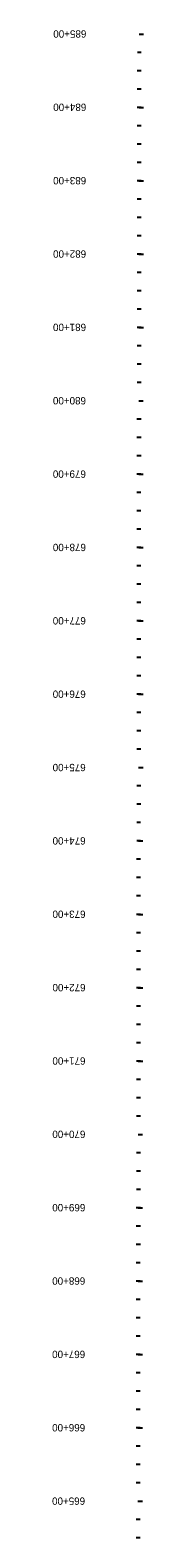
# Model space of a CAD drawing. Extents: x 16453950 to 16454580, y 7022804 to 7039381.
# Drawn here: x 16454323 to 16454448, y 7033190 to 7035245 of the extents above; entities that cross this region are included whole.
import ezdxf

# ---------------------------------------------------------------- set-up
doc = ezdxf.new("R2010")
doc.units = 0
doc.layers.add('TextAlignmentLrg', color=7, linetype='Continuous')
doc.layers.add('TextAlignmentSml', color=7, linetype='Continuous')

msp = doc.modelspace()

# ---------------------------------------------------------------- linework, layer by layer
at = {"layer": 'TextAlignmentLrg'}
for p, q in [((16454441.5, 7035239.6), (16454447.6, 7035239.6)), ((16454444.5, 7035139.6), (16454439, 7035139.6)), ((16454444.4, 7035039.6), (16454438.9, 7035039.6)), ((16454444.3, 7034939.6), (16454438.8, 7034939.6)), ((16454444.2, 7034839.6), (16454438.8, 7034839.6)), ((16454441.1, 7034739.6), (16454447.2, 7034739.6)), ((16454444, 7034639.6), (16454438.6, 7034639.6)), ((16454444, 7034539.6), (16454438.5, 7034539.6)), ((16454443.9, 7034439.6), (16454438.4, 7034439.6)), ((16454443.8, 7034339.6), (16454438.3, 7034339.6)), ((16454440.6, 7034239.6), (16454446.8, 7034239.6)), ((16454443.6, 7034139.6), (16454438.2, 7034139.6)), ((16454443.5, 7034039.6), (16454438.1, 7034039.6)), ((16454443.5, 7033939.6), (16454438, 7033939.6)), ((16454443.4, 7033839.6), (16454437.9, 7033839.6)), ((16454440.2, 7033739.6), (16454446.3, 7033739.6)), ((16454443.2, 7033639.6), (16454437.7, 7033639.6)), ((16454443.1, 7033539.6), (16454437.7, 7033539.6)), ((16454443, 7033439.6), (16454437.6, 7033439.6)), ((16454442.9, 7033339.6), (16454437.5, 7033339.6)), ((16454439.8, 7033239.6), (16454445.9, 7033239.6))]:
    msp.add_line(p, q, dxfattribs=at)
at = {"layer": 'TextAlignmentSml'}
for p, q in [((16454441.5, 7035239.6), (16454447.6, 7035239.6)), ((16454444.5, 7035214.6), (16454439.1, 7035214.6)), ((16454444.5, 7035189.6), (16454439, 7035189.6)), ((16454444.5, 7035164.6), (16454439, 7035164.6)), ((16454441.4, 7035139.6), (16454447.5, 7035139.6)), ((16454444.4, 7035114.6), (16454439, 7035114.6)), ((16454444.4, 7035089.6), (16454439, 7035089.6)), ((16454444.4, 7035064.6), (16454438.9, 7035064.6)), ((16454441.3, 7035039.6), (16454447.4, 7035039.6)), ((16454444.4, 7035014.6), (16454438.9, 7035014.6)), ((16454444.3, 7034989.6), (16454438.9, 7034989.6)), ((16454444.3, 7034964.6), (16454438.9, 7034964.6)), ((16454441.2, 7034939.6), (16454447.4, 7034939.6)), ((16454444.3, 7034914.6), (16454438.8, 7034914.6)), ((16454444.3, 7034889.6), (16454438.8, 7034889.6)), ((16454444.2, 7034864.6), (16454438.8, 7034864.6)), ((16454441.2, 7034839.6), (16454447.3, 7034839.6)), ((16454444.2, 7034814.6), (16454438.7, 7034814.6)), ((16454444.2, 7034789.6), (16454438.7, 7034789.6)), ((16454444.1, 7034764.6), (16454438.7, 7034764.6)), ((16454441.1, 7034739.6), (16454447.2, 7034739.6)), ((16454444.1, 7034714.6), (16454438.6, 7034714.6)), ((16454444.1, 7034689.6), (16454438.6, 7034689.6)), ((16454444.1, 7034664.6), (16454438.6, 7034664.6)), ((16454441, 7034639.6), (16454447.1, 7034639.6)), ((16454444, 7034614.6), (16454438.6, 7034614.6)), ((16454444, 7034589.6), (16454438.5, 7034589.6)), ((16454444, 7034564.6), (16454438.5, 7034564.6)), ((16454440.9, 7034539.6), (16454447, 7034539.6)), ((16454443.9, 7034514.6), (16454438.5, 7034514.6)), ((16454443.9, 7034489.6), (16454438.5, 7034489.6)), ((16454443.9, 7034464.6), (16454438.4, 7034464.6)), ((16454440.8, 7034439.6), (16454446.9, 7034439.6)), ((16454443.9, 7034414.6), (16454438.4, 7034414.6)), ((16454443.8, 7034389.6), (16454438.4, 7034389.6)), ((16454443.8, 7034364.6), (16454438.4, 7034364.6)), ((16454440.7, 7034339.6), (16454446.9, 7034339.6)), ((16454443.8, 7034314.6), (16454438.3, 7034314.6)), ((16454443.7, 7034289.6), (16454438.3, 7034289.6)), ((16454443.7, 7034264.6), (16454438.3, 7034264.6)), ((16454440.6, 7034239.6), (16454446.8, 7034239.6)), ((16454443.7, 7034214.6), (16454438.2, 7034214.6)), ((16454443.7, 7034189.6), (16454438.2, 7034189.6)), ((16454443.6, 7034164.6), (16454438.2, 7034164.6)), ((16454440.6, 7034139.6), (16454446.7, 7034139.6)), ((16454443.6, 7034114.6), (16454438.1, 7034114.6)), ((16454443.6, 7034089.6), (16454438.1, 7034089.6)), ((16454443.6, 7034064.6), (16454438.1, 7034064.6)), ((16454440.5, 7034039.6), (16454446.6, 7034039.6)), ((16454443.5, 7034014.6), (16454438.1, 7034014.6)), ((16454443.5, 7033989.6), (16454438, 7033989.6)), ((16454443.5, 7033964.6), (16454438, 7033964.6)), ((16454440.4, 7033939.6), (16454446.5, 7033939.6)), ((16454443.4, 7033914.6), (16454438, 7033914.6)), ((16454443.4, 7033889.6), (16454438, 7033889.6)), ((16454443.4, 7033864.6), (16454437.9, 7033864.6)), ((16454440.3, 7033839.6), (16454446.4, 7033839.6)), ((16454443.3, 7033814.6), (16454437.9, 7033814.6)), ((16454443.3, 7033789.6), (16454437.9, 7033789.6)), ((16454443.3, 7033764.6), (16454437.8, 7033764.6)), ((16454440.2, 7033739.6), (16454446.3, 7033739.6)), ((16454443.3, 7033714.6), (16454437.8, 7033714.6)), ((16454443.2, 7033689.6), (16454437.8, 7033689.6)), ((16454443.2, 7033664.6), (16454437.8, 7033664.6)), ((16454440.1, 7033639.6), (16454446.3, 7033639.6)), ((16454443.2, 7033614.6), (16454437.7, 7033614.6)), ((16454443.2, 7033589.6), (16454437.7, 7033589.6)), ((16454443.1, 7033564.6), (16454437.7, 7033564.6)), ((16454440.1, 7033539.6), (16454446.2, 7033539.6)), ((16454443.1, 7033514.6), (16454437.6, 7033514.6)), ((16454443.1, 7033489.6), (16454437.6, 7033489.6)), ((16454443.1, 7033464.6), (16454437.6, 7033464.6)), ((16454440, 7033439.6), (16454446.1, 7033439.6)), ((16454443, 7033414.6), (16454437.5, 7033414.6)), ((16454443, 7033389.6), (16454437.5, 7033389.6)), ((16454443, 7033364.6), (16454437.5, 7033364.6)), ((16454439.9, 7033339.6), (16454446, 7033339.6)), ((16454442.9, 7033314.6), (16454437.5, 7033314.6)), ((16454442.9, 7033289.6), (16454437.4, 7033289.6)), ((16454442.9, 7033264.6), (16454437.4, 7033264.6)), ((16454439.8, 7033239.6), (16454445.9, 7033239.6)), ((16454442.8, 7033214.6), (16454437.4, 7033214.6)), ((16454442.8, 7033189.6), (16454437.4, 7033189.6))]:
    msp.add_line(p, q, dxfattribs=at)

# ---------------------------------------------------------------- texts
at = {"layer": 'TextAlignmentLrg'}
for s, p in [('685+00', (16454369.6, 7035244.7)), ('680+00', (16454369.1, 7034744.7)), ('675+00', (16454368.7, 7034244.7)), ('670+00', (16454368.3, 7033744.7)), ('665+00', (16454367.9, 7033244.7))]:
    msp.add_text(s, height=10.02, rotation=179.9517, dxfattribs=at).set_placement(p)
at = {"layer": 'TextAlignmentSml'}
for s, p in [('685+00', (16454369.6, 7035244.7)), ('684+00', (16454369.5, 7035144.7)), ('683+00', (16454369.4, 7035044.7)), ('682+00', (16454369.3, 7034944.7)), ('681+00', (16454369.2, 7034844.7)), ('680+00', (16454369.1, 7034744.7)), ('679+00', (16454369, 7034644.7)), ('678+00', (16454369, 7034544.7)), ('677+00', (16454368.9, 7034444.7)), ('676+00', (16454368.8, 7034344.7)), ('675+00', (16454368.7, 7034244.7)), ('674+00', (16454368.6, 7034144.7)), ('673+00', (16454368.5, 7034044.7)), ('672+00', (16454368.5, 7033944.7)), ('671+00', (16454368.4, 7033844.7)), ('670+00', (16454368.3, 7033744.7)), ('669+00', (16454368.2, 7033644.7)), ('668+00', (16454368.1, 7033544.7)), ('667+00', (16454368, 7033444.7)), ('666+00', (16454368, 7033344.7)), ('665+00', (16454367.9, 7033244.7))]:
    msp.add_text(s, height=10.02, rotation=179.9517, dxfattribs=at).set_placement(p)

doc.saveas('drawing.dxf')
